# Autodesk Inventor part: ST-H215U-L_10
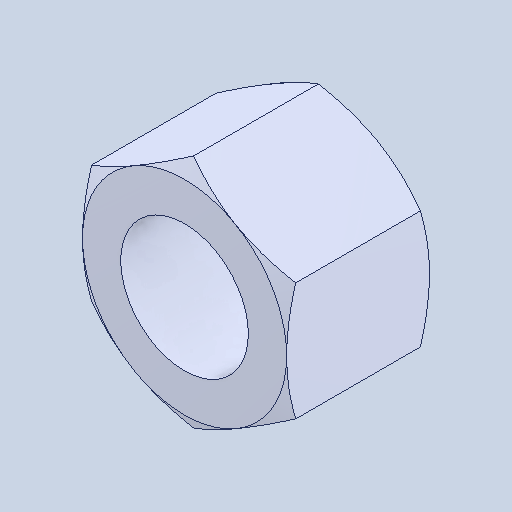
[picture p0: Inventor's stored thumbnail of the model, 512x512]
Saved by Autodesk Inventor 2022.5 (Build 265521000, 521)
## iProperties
Created: 2024-07
Part Number: ST-H215U-L_10
Material: 一般
Document SubType Name: Modeling
Designer: ImaoCorp
Density: 1 g/cm^3
Appearance: 既定
Author: ImaoCorp
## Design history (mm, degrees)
feature "ST-H215U-L_10"
node "ソリッド1"
